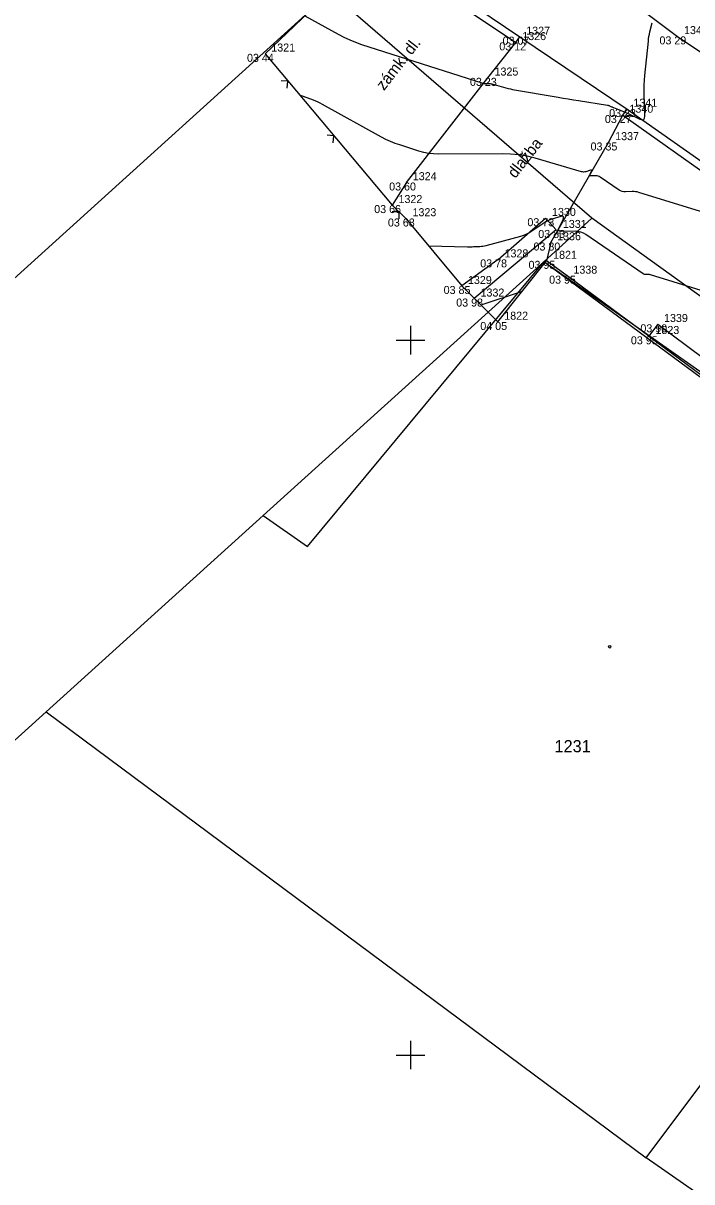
# Model space of a CAD drawing. Extents: x -711234 to -710007, y -1026313 to -1025448.
# Drawn here: x -710588.55 to -710565.16, y -1025579.43 to -1025538.91 of the extents above; entities that cross this region are included whole.
import ezdxf

# ---------------------------------------------------------------- set-up
doc = ezdxf.new("R2010")
doc.units = 0
for name, color, linetype in [('Ex_Major Contours', 7, 'Continuous'), ('Ex_Minor Contours', 7, 'Continuous'), ('Z_body', 7, 'Continuous'), ('Z_body_cisla', 7, 'Continuous'), ('Z_body_vysky_redukovane', 7, 'Continuous'), ('Z_budova', 7, 'Continuous'), ('Z_hektometricka_sit', 7, 'Continuous'), ('Z_katastr_cisla_stavebni', 7, 'Continuous'), ('Z_katastr_hranice', 7, 'Continuous'), ('Z_katastr_vnitrni_kresba', 7, 'Continuous'), ('Z_katastr_znacky_budov', 7, 'Continuous'), ('Z_komunikace', 7, 'Continuous'), ('Z_komunikace_osa', 7, 'Continuous'), ('Z_obruba', 7, 'Continuous'), ('Z_ploty', 7, 'Continuous'), ('Z_ploty_znacky', 7, 'Continuous'), ('Z_popisy', 7, 'Continuous'), ('Z_rozhranni', 7, 'Continuous'), ('Z_vstupy', 7, 'Continuous')]:
    doc.layers.add(name, color=color, linetype=linetype)

# ---------------------------------------------------------------- blocks, each defined once
blk = doc.blocks.new('POINT_DISPLAY')
blk.add_line((0, 0), (0, 0))
blk = doc.blocks.new('Z212')
for p, q in [((-0.17, 0.17), (0, 0)), ((0, 0), (0.17, 0.17))]:
    blk.add_line(p, q)

msp = doc.modelspace()

# ---------------------------------------------------------------- linework, layer by layer
at = {"layer": 'Ex_Major Contours'}
msp.add_lwpolyline([(-710571.095, -1025548.29), (-710572.536, -1025548.774)], dxfattribs=at)
at = {"layer": 'Ex_Minor Contours'}
for points in [[(-710578.699, -1025538.65), (-710577.526, -1025539.297), (-710577.329, -1025539.4), (-710577.127, -1025539.493), (-710576.921, -1025539.576), (-710576.711, -1025539.649), (-710572.5, -1025541), (-710572.472, -1025541.008), (-710572.443, -1025541.013), (-710572.415, -1025541.017), (-710572.385, -1025541.017), (-710572.268, -1025541.017), (-710572.239, -1025541.018), (-710572.21, -1025541.021), (-710572.182, -1025541.026), (-710572.153, -1025541.033), (-710571.742, -1025541.152), (-710571.664, -1025541.173), (-710571.586, -1025541.192), (-710571.507, -1025541.209), (-710571.427, -1025541.224), (-710569.83, -1025541.498), (-710569.655, -1025541.528), (-710569.479, -1025541.557), (-710569.302, -1025541.586), (-710569.126, -1025541.614), (-710568.106, -1025541.775), (-710568.088, -1025541.779), (-710568.069, -1025541.784), (-710568.052, -1025541.79), (-710568.034, -1025541.798), (-710567.965, -1025541.83), (-710567.947, -1025541.838), (-710567.93, -1025541.845), (-710567.912, -1025541.853), (-710567.894, -1025541.86), (-710567.604, -1025541.973), (-710567.55, -1025541.994), (-710567.496, -1025542.017), (-710567.443, -1025542.041), (-710567.39, -1025542.066), (-710566.971, -1025542.267), (-710566.895, -1025542.291), (-710566.842, -1025542.281), (-710566.811, -1025542.236), (-710566.802, -1025542.157), (-710566.824, -1025541.385), (-710566.826, -1025541.224), (-710566.823, -1025541.064), (-710566.814, -1025540.903), (-710566.801, -1025540.743), (-710566.678, -1025539.535), (-710566.669, -1025539.454), (-710566.657, -1025539.373), (-710566.642, -1025539.292), (-710566.624, -1025539.212), (-710566.549, -1025538.891)], [(-710561.827, -1025546.43), (-710567.011, -1025544.828), (-710567.068, -1025544.813), (-710567.126, -1025544.803), (-710567.184, -1025544.798), (-710567.244, -1025544.798), (-710567.482, -1025544.809), (-710567.54, -1025544.807), (-710567.596, -1025544.796), (-710567.649, -1025544.776), (-710567.699, -1025544.747), (-710568.368, -1025544.289), (-710568.401, -1025544.27), (-710568.436, -1025544.256), (-710568.472, -1025544.248), (-710568.51, -1025544.245), (-710568.685, -1025544.246), (-710568.709, -1025544.243), (-710568.722, -1025544.233), (-710568.725, -1025544.217), (-710568.718, -1025544.194), (-710568.667, -1025544.089), (-710568.66, -1025544.067), (-710568.662, -1025544.054), (-710568.675, -1025544.049), (-710568.698, -1025544.053), (-710568.867, -1025544.104), (-710568.905, -1025544.112), (-710568.942, -1025544.115), (-710568.98, -1025544.112), (-710569.018, -1025544.104), (-710570.639, -1025543.635), (-710570.923, -1025543.564), (-710571.21, -1025543.513), (-710571.5, -1025543.484), (-710571.793, -1025543.475), (-710574.018, -1025543.489), (-710574.193, -1025543.483), (-710574.366, -1025543.463), (-710574.536, -1025543.43), (-710574.705, -1025543.383), (-710575.375, -1025543.168), (-710575.541, -1025543.111), (-710575.703, -1025543.045), (-710575.863, -1025542.972), (-710576.018, -1025542.891), (-710578.083, -1025541.751), (-710578.159, -1025541.71), (-710578.236, -1025541.673), (-710578.315, -1025541.638), (-710578.394, -1025541.606), (-710578.876, -1025541.423)], [(-710560.712, -1025549.529), (-710566.598, -1025547.71), (-710566.619, -1025547.705), (-710566.641, -1025547.701), (-710566.663, -1025547.699), (-710566.685, -1025547.699), (-710566.774, -1025547.703), (-710566.796, -1025547.703), (-710566.817, -1025547.699), (-710566.837, -1025547.691), (-710566.856, -1025547.68), (-710568.866, -1025546.304), (-710568.953, -1025546.253), (-710569.046, -1025546.216), (-710569.143, -1025546.195), (-710569.244, -1025546.188), (-710569.71, -1025546.19), (-710569.774, -1025546.182), (-710569.81, -1025546.156), (-710569.818, -1025546.112), (-710569.798, -1025546.051), (-710569.663, -1025545.77), (-710569.642, -1025545.712), (-710569.649, -1025545.676), (-710569.683, -1025545.664), (-710569.744, -1025545.675), (-710570.052, -1025545.767), (-710570.127, -1025545.792), (-710570.199, -1025545.823), (-710570.269, -1025545.859), (-710570.336, -1025545.901), (-710570.756, -1025546.183), (-710570.85, -1025546.24), (-710570.947, -1025546.29), (-710571.049, -1025546.331), (-710571.154, -1025546.364), (-710572.36, -1025546.693), (-710572.413, -1025546.706), (-710572.466, -1025546.716), (-710572.519, -1025546.723), (-710572.574, -1025546.727), (-710572.791, -1025546.736), (-710572.845, -1025546.738), (-710572.899, -1025546.739), (-710572.953, -1025546.739), (-710573.008, -1025546.739), (-710574.357, -1025546.712)]]:
    msp.add_lwpolyline(points, dxfattribs=at)
at = {"layer": 'Z_budova'}
for p, q in [((-710571.95, -1025549.36), (-710570.24, -1025547.22)), ((-710569.52, -1025547.74), (-710570.24, -1025547.22)), ((-710566.66, -1025549.86), (-710557.38, -1025556.71))]:
    msp.add_line(p, q, dxfattribs=at)
at = {"layer": 'Z_hektometricka_sit'}
for p, q in [((-710575, -1025549.5), (-710575, -1025550.5)), ((-710575.5, -1025550), (-710574.5, -1025550)), ((-710575, -1025574.5), (-710575, -1025575.5)), ((-710575.5, -1025575), (-710574.5, -1025575))]:
    msp.add_line(p, q, dxfattribs=at)
at = {"layer": 'Z_katastr_hranice'}
for p, q in [((-710568.66, -1025545.73), (-710577.81, -1025537.82)), ((-710570.34, -1025547.25), (-710568.66, -1025545.73)), ((-710521.34, -1025581.73), (-710570.34, -1025547.25)), ((-710587.75, -1025563), (-710566.76, -1025578.6))]:
    msp.add_line(p, q, dxfattribs=at)
for points in [[(-710577.81, -1025537.82), (-710614.99, -1025571.47), (-710648.25, -1025532.06), (-710620.52, -1025511.94)], [(-710507.35, -1025589.15), (-710543.35, -1025563.94), (-710568.66, -1025545.73)], [(-710570.34, -1025547.25), (-710580.15, -1025556.13), (-710587.75, -1025563)], [(-710566.76, -1025578.6), (-710563.9, -1025574.78), (-710556, -1025580.54), (-710552.84, -1025576.25), (-710556.83, -1025573.35), (-710553.5, -1025568.74), (-710552.54, -1025569.47), (-710550.71, -1025567.17), (-710549.72, -1025566.86), (-710547.43, -1025564.15), (-710570.34, -1025547.25)], [(-710536.69, -1025630.33), (-710607.26, -1025580.65), (-710587.75, -1025563)], [(-710521.34, -1025581.73), (-710522.06, -1025583.11), (-710524.84, -1025588.43), (-710517.09, -1025594.28), (-710526.76, -1025607.58), (-710531.49, -1025604.04), (-710531.7, -1025604.35), (-710562.31, -1025581.82), (-710566.38, -1025587.58), (-710568.9, -1025585.73), (-710564.8, -1025579.96), (-710566.76, -1025578.6)]]:
    msp.add_lwpolyline(points, dxfattribs=at)
at = {"layer": 'Z_katastr_vnitrni_kresba'}
msp.add_lwpolyline([(-710580.15, -1025556.13), (-710578.6, -1025557.21), (-710570.34, -1025547.25)], dxfattribs=at)
at = {"layer": 'Z_katastr_znacky_budov'}
msp.add_circle((-710568.032, -1025560.72), 0.0437, dxfattribs=at)
at = {"layer": 'Z_komunikace'}
for p, q in [((-710576.16, -1025536.02), (-710571.17, -1025539.38)), ((-710571.17, -1025539.38), (-710567.42, -1025541.91)), ((-710567.42, -1025541.91), (-710556.51, -1025549.62))]:
    msp.add_line(p, q, dxfattribs=at)
at = {"layer": 'Z_komunikace_osa'}
for p, q in [((-710572.26, -1025534.42), (-710565.66, -1025539.37)), ((-710565.66, -1025539.37), (-710554.43, -1025546.96))]:
    msp.add_line(p, q, dxfattribs=at)
at = {"layer": 'Z_obruba'}
for p, q in [((-710576.38, -1025536.2), (-710571.31, -1025539.58)), ((-710571.31, -1025539.58), (-710571.17, -1025539.38)), ((-710567.57, -1025542.12), (-710567.42, -1025541.91)), ((-710567.57, -1025542.12), (-710556.66, -1025549.9))]:
    msp.add_line(p, q, dxfattribs=at)
at = {"layer": 'Z_ploty'}
for p, q in [((-710577.82, -1025537.81), (-710580.09, -1025539.98)), ((-710580.09, -1025539.98), (-710575.64, -1025545.27)), ((-710575.64, -1025545.27), (-710575.16, -1025545.74))]:
    msp.add_line(p, q, dxfattribs=at)
at = {"layer": 'Z_rozhranni'}
for p, q in [((-710572.29, -1025540.82), (-710571.31, -1025539.58)), ((-710575.14, -1025544.48), (-710572.29, -1025540.82)), ((-710568.07, -1025543.08), (-710567.57, -1025542.12)), ((-710570.09, -1025546.58), (-710568.07, -1025543.08)), ((-710575.14, -1025544.48), (-710575.64, -1025545.27)), ((-710571.93, -1025547.17), (-710570.28, -1025545.73)), ((-710570.28, -1025545.73), (-710569.9, -1025546.14)), ((-710569.9, -1025546.14), (-710572.77, -1025548.54)), ((-710570.09, -1025546.58), (-710570.24, -1025547.22)), ((-710571.93, -1025547.17), (-710573.21, -1025548.1)), ((-710566.35, -1025549.44), (-710566.66, -1025549.86)), ((-710566.35, -1025549.44), (-710559.8, -1025554.31))]:
    msp.add_line(p, q, dxfattribs=at)
at = {"layer": 'Z_vstupy'}
for p, q in [((-710575.16, -1025545.74), (-710573.21, -1025548.1)), ((-710566.66, -1025549.86), (-710569.52, -1025547.74)), ((-710573.21, -1025548.1), (-710571.95, -1025549.36))]:
    msp.add_line(p, q, dxfattribs=at)

# ---------------------------------------------------------------- block references
at = {"layer": 'Z_body'}
for p in [(-710571.17, -1025539.38), (-710565.66, -1025539.37), (-710571.31, -1025539.58), (-710580.09, -1025539.98), (-710572.29, -1025540.82), (-710567.57, -1025542.12), (-710567.42, -1025541.91), (-710568.07, -1025543.08), (-710575.14, -1025544.48), (-710575.64, -1025545.27), (-710575.16, -1025545.74), (-710570.28, -1025545.73), (-710569.9, -1025546.14), (-710570.09, -1025546.58), (-710571.93, -1025547.17), (-710570.24, -1025547.22), (-710569.52, -1025547.74), (-710573.21, -1025548.1), (-710572.77, -1025548.54), (-710571.95, -1025549.36), (-710566.35, -1025549.44), (-710566.66, -1025549.86)]:
    msp.add_blockref('POINT_DISPLAY', p, dxfattribs=at)
at = {"layer": 'Z_ploty_znacky'}
for p, rotation in [((-710579.29, -1025540.94), 130.1), ((-710577.68, -1025542.85), 130.1), ((-710575.4, -1025545.51), 135.6)]:
    msp.add_blockref('Z212', p, dxfattribs=dict(at, rotation=rotation))

# ---------------------------------------------------------------- texts
at = {"layer": 'Z_body_cisla'}
for s, p in [('1327', (-710570.95, -1025539.31)), ('1342', (-710565.43, -1025539.29)), ('1326', (-710571.09, -1025539.5)), ('1321', (-710579.87, -1025539.9)), ('1325', (-710572.06, -1025540.74)), ('1340', (-710567.34, -1025542.04)), ('1341', (-710567.2, -1025541.83)), ('1337', (-710567.84, -1025543)), ('1324', (-710574.92, -1025544.4)), ('1322', (-710575.42, -1025545.2)), ('1323', (-710574.93, -1025545.66)), ('1330', (-710570.05, -1025545.65)), ('1331', (-710569.67, -1025546.07)), ('1336', (-710569.87, -1025546.5)), ('1328', (-710571.71, -1025547.1)), ('1821', (-710570.01, -1025547.15)), ('1338', (-710569.3, -1025547.67)), ('1329', (-710572.99, -1025548.03)), ('1332', (-710572.55, -1025548.47)), ('1822', (-710571.72, -1025549.28)), ('1339', (-710566.13, -1025549.36)), ('1823', (-710566.43, -1025549.78))]:
    msp.add_text(s, height=0.28, dxfattribs=at).set_placement(p)
at = {"layer": 'Z_body_vysky_redukovane'}
for s, p in [('03 07', (-710571.777, -1025539.66)), ('03 29', (-710566.29, -1025539.65)), ('03 12', (-710571.893, -1025539.86)), ('03 44', (-710580.72, -1025540.26)), ('03 23', (-710572.92, -1025541.1)), ('03 27', (-710568.2, -1025542.4)), ('03 23', (-710568.05, -1025542.19)), ('03 35', (-710568.7, -1025543.36)), ('03 60', (-710575.747, -1025544.76)), ('03 66', (-710576.27, -1025545.55)), ('03 68', (-710575.79, -1025546.02)), ('03 73', (-710570.91, -1025546.01)), ('03 83', (-710570.53, -1025546.42)), ('03 80', (-710570.697, -1025546.86)), ('03 78', (-710572.56, -1025547.45)), ('03 95', (-710570.87, -1025547.5)), ('03 95', (-710570.15, -1025548.02)), ('03 85', (-710573.84, -1025548.38)), ('03 98', (-710573.4, -1025548.82)), ('04 05', (-710572.557, -1025549.64)), ('03 90', (-710566.957, -1025549.72)), ('03 95', (-710567.29, -1025550.14))]:
    msp.add_text(s, height=0.28, dxfattribs=at).set_placement(p)
at = {"layer": 'Z_katastr_cisla_stavebni'}
msp.add_text('1231', height=0.425, dxfattribs=at).set_placement((-710569.96, -1025564.41))
at = {"layer": 'Z_popisy'}
for s, p in [('zámk. dl.', (-710575.93, -1025541.29)), ('dlažba', (-710571.33, -1025544.36))]:
    msp.add_text(s, height=0.4, rotation=52.2, dxfattribs=at).set_placement(p)

doc.saveas('drawing.dxf')
